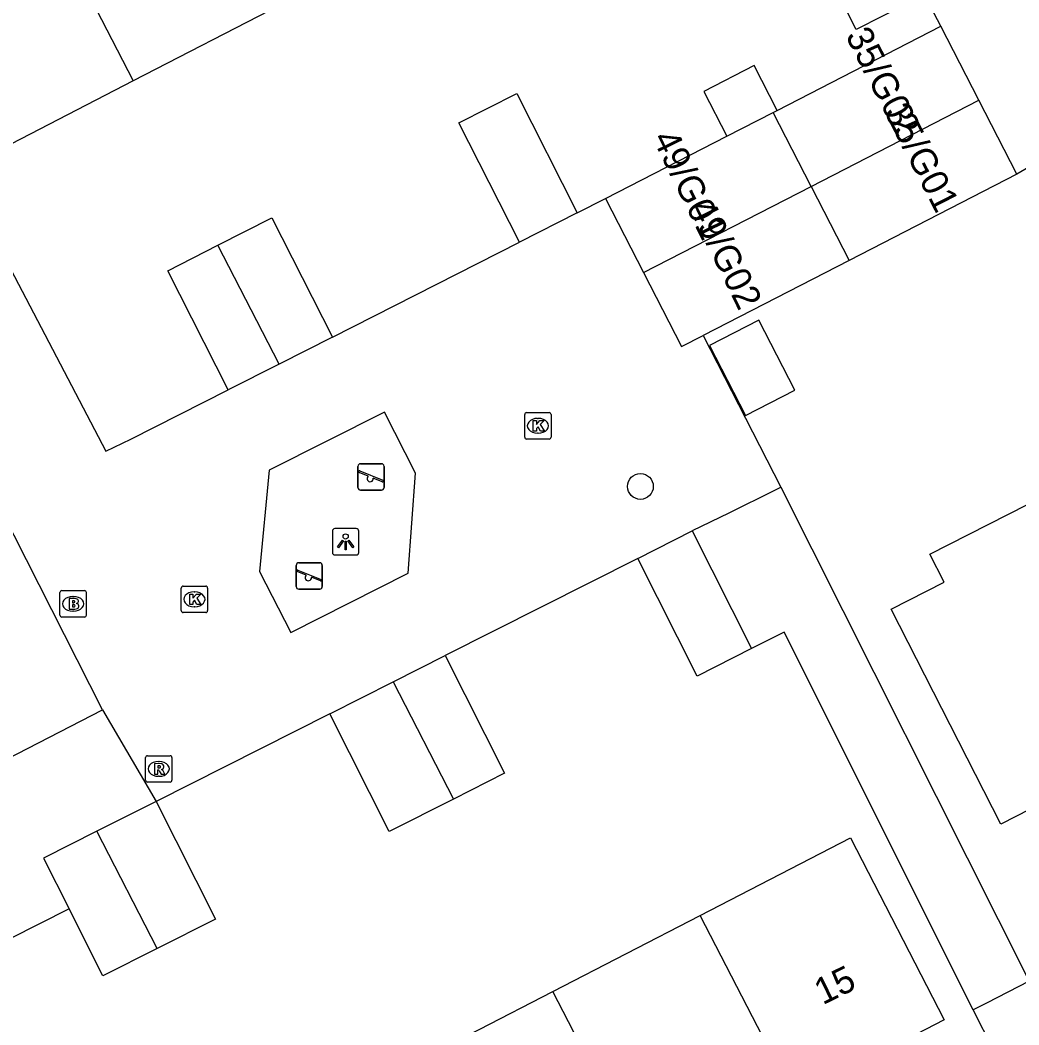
# Model space of a CAD drawing. Extents: x 158461 to 159795, y 387220 to 388672.
# Drawn here: x 159193.22 to 159231.02, y 387806.3 to 387844.32 of the extents above; entities that cross this region are included whole.
import ezdxf

# ---------------------------------------------------------------- set-up
doc = ezdxf.new("R2010")
doc.units = 0
for name, color, linetype in [('IMGEO_Boom', 7, 'Continuous'), ('IMGEO_Brandkraan', 7, 'Continuous'), ('IMGEO_Kolk', 7, 'Continuous'), ('IMGEO_Lichtpunt', 7, 'Continuous'), ('IMGEO_Pand', 7, 'Continuous'), ('IMGEO_Pand_nummerreeks', 7, 'Continuous'), ('IMGEO_Rijbaan_lokaal_open', 7, 'Continuous'), ('IMGEO_Rioolput', 7, 'Continuous'), ('IMGEO_Speelvoorziening', 7, 'Continuous'), ('IMGEO_Voetpad_open', 7, 'Continuous')]:
    doc.layers.add(name, color=color, linetype=linetype)

msp = doc.modelspace()

# ---------------------------------------------------------------- linework, layer by layer
at = {"layer": 'IMGEO_Boom'}
msp.add_circle((159216.693, 387826.671), 0.489, dxfattribs=at)
at = {"layer": 'IMGEO_Brandkraan'}
for p, q in [((159194.797, 387822.728), (159195.649, 387822.728)), ((159194.722, 387821.802), (159194.722, 387822.654)), ((159195.21, 387822.508), (159195.235, 387822.508)), ((159195.723, 387822.654), (159195.723, 387821.802)), ((159195.649, 387821.728), (159194.797, 387821.728)), ((159195.233, 387821.948), (159195.208, 387821.948))]:
    msp.add_line(p, q, dxfattribs=at)
for points in [[(159194.797, 387822.728), (159195.649, 387822.728)], [(159194.722, 387821.802), (159194.722, 387822.654)], [(159195.07, 387822.428), (159195.07, 387822.028), (159195.283, 387822.028)], [(159195.301, 387822.428), (159195.07, 387822.428)], [(159195.249, 387822.347), (159195.195, 387822.347), (159195.195, 387822.271)], [(159195.723, 387822.654), (159195.723, 387821.802)], [(159195.195, 387822.271), (159195.248, 387822.271)], [(159195.257, 387822.195), (159195.195, 387822.195), (159195.195, 387822.114)], [(159195.195, 387822.114), (159195.257, 387822.114)], [(159195.649, 387821.728), (159194.797, 387821.728)]]:
    msp.add_lwpolyline(points, dxfattribs=at)
for centre, radius, start, end in [((159194.799, 387822.652), 0.0765, 91.552, 178.448), ((159194.799, 387822.652), 0.0765, 91.552, 178.448), ((159195.647, 387822.652), 0.0765, 1.552, 88.448), ((159195.647, 387822.652), 0.0765, 1.552, 88.448), ((159195.25, 387822.309), 0.0379, 267.8285, 90.9355), ((159195.305, 387822.283), 0.145, 59.4692, 91.5367), ((159195.33, 387822.33), 0.0922, 285.5137, 58.1501), ((159195.258, 387822.154), 0.0404, 269.8759, 90.5077), ((159195.289, 387822.279), 0.251, 268.6676, 293.5347), ((159195.335, 387822.138), 0.105, 301.3115, 78.989), ((159194.799, 387821.804), 0.0765, 181.552, 268.448), ((159194.799, 387821.804), 0.0765, 181.552, 268.448), ((159195.647, 387821.804), 0.0765, 271.552, 358.448), ((159195.647, 387821.804), 0.0765, 271.552, 358.448)]:
    msp.add_arc(centre, radius, start, end, dxfattribs=at)
for centre, major_axis, ratio, start_param, end_param in [((159195.209, 387822.228), (-0.387, 0.002), 0.722429, 4.712389, 7.853982), ((159195.234, 387822.228), (-0.39, 0.002), 0.717154, 1.570796, 4.712389)]:
    msp.add_ellipse(centre, major_axis=major_axis, ratio=ratio, start_param=start_param, end_param=end_param, dxfattribs=at)
at = {"layer": 'IMGEO_Kolk'}
for p, q in [((159212.313, 387828.539), (159212.313, 387829.391)), ((159212.388, 387829.465), (159213.24, 387829.465)), ((159212.801, 387829.245), (159212.826, 387829.245)), ((159213.314, 387829.391), (159213.314, 387828.539)), ((159213.24, 387828.465), (159212.388, 387828.465)), ((159212.824, 387828.685), (159212.799, 387828.685)), ((159199.313, 387821.972), (159199.313, 387822.824)), ((159199.388, 387822.898), (159200.24, 387822.898)), ((159200.314, 387822.824), (159200.314, 387821.972)), ((159199.801, 387822.678), (159199.826, 387822.678)), ((159199.824, 387822.118), (159199.799, 387822.118)), ((159200.24, 387821.898), (159199.388, 387821.898))]:
    msp.add_line(p, q, dxfattribs=at)
for points in [[(159212.313, 387828.539), (159212.313, 387829.391)], [(159212.388, 387829.465), (159213.24, 387829.465)], [(159213.314, 387829.391), (159213.314, 387828.539)], [(159212.634, 387829.165), (159212.757, 387829.165), (159212.757, 387829.014), (159212.887, 387829.165), (159213.051, 387829.165), (159212.905, 387829.014), (159213.058, 387828.765), (159212.906, 387828.765), (159212.821, 387828.929), (159212.757, 387828.862), (159212.757, 387828.765), (159212.634, 387828.765), (159212.634, 387829.165)], [(159213.24, 387828.465), (159212.388, 387828.465)], [(159199.313, 387821.972), (159199.313, 387822.824)], [(159199.388, 387822.898), (159200.24, 387822.898)], [(159200.314, 387822.824), (159200.314, 387821.972)], [(159199.634, 387822.598), (159199.757, 387822.598), (159199.757, 387822.447), (159199.887, 387822.598), (159200.051, 387822.598), (159199.905, 387822.447), (159200.058, 387822.198), (159199.906, 387822.198), (159199.821, 387822.362), (159199.757, 387822.295), (159199.757, 387822.198), (159199.634, 387822.198), (159199.634, 387822.598)], [(159200.24, 387821.898), (159199.388, 387821.898)]]:
    msp.add_lwpolyline(points, dxfattribs=at)
for centre, start, end in [((159212.39, 387829.389), 91.552, 178.448), ((159212.39, 387829.389), 91.552, 178.448), ((159213.238, 387829.389), 1.552, 88.448), ((159213.238, 387829.389), 1.552, 88.448), ((159212.39, 387828.541), 181.552, 268.448), ((159212.39, 387828.541), 181.552, 268.448), ((159213.238, 387828.541), 271.552, 358.448), ((159213.238, 387828.541), 271.552, 358.448), ((159199.39, 387822.822), 91.552, 178.448), ((159199.39, 387822.822), 91.552, 178.448), ((159200.238, 387822.822), 1.552, 88.448), ((159200.238, 387822.822), 1.552, 88.448), ((159199.39, 387821.974), 181.552, 268.448), ((159199.39, 387821.974), 181.552, 268.448), ((159200.238, 387821.974), 271.552, 358.448), ((159200.238, 387821.974), 271.552, 358.448)]:
    msp.add_arc(centre, 0.0765, start, end, dxfattribs=at)
for centre, major_axis, ratio, start_param, end_param in [((159212.8, 387828.965), (-0.387, 0.002), 0.722429, 4.712389, 7.853982), ((159212.825, 387828.965), (-0.39, 0.002), 0.717154, 1.570796, 4.712389), ((159199.8, 387822.398), (-0.387, 0.002), 0.722429, 4.712389, 7.853982), ((159199.825, 387822.398), (-0.39, 0.002), 0.717154, 1.570796, 4.712389)]:
    msp.add_ellipse(centre, major_axis=major_axis, ratio=ratio, start_param=start_param, end_param=end_param, dxfattribs=at)
at = {"layer": 'IMGEO_Lichtpunt'}
for p, q in [((159205.94, 387825.074), (159205.132, 387825.074)), ((159205.94, 387825.074), (159205.132, 387825.074)), ((159205.038, 387824.979), (159205.038, 387824.172)), ((159205.038, 387824.979), (159205.038, 387824.172)), ((159206.034, 387824.172), (159206.034, 387824.979)), ((159206.034, 387824.172), (159206.034, 387824.979)), ((159205.132, 387824.078), (159205.94, 387824.078)), ((159205.132, 387824.078), (159205.94, 387824.078))]:
    msp.add_line(p, q, dxfattribs=at)
for points in [[(159205.412, 387824.643), (159205.451, 387824.615), (159205.263, 387824.353), (159205.225, 387824.38), (159205.412, 387824.643)], [(159205.624, 387824.615), (159205.662, 387824.642), (159205.849, 387824.38), (159205.81, 387824.352), (159205.624, 387824.615)], [(159205.514, 387824.595), (159205.561, 387824.595), (159205.561, 387824.273), (159205.514, 387824.273), (159205.514, 387824.595)]]:
    msp.add_lwpolyline(points, dxfattribs=at)
msp.add_circle((159205.537, 387824.777), 0.0994, dxfattribs=at)
for centre, start, end in [((159205.132, 387824.979), 90, 180), ((159205.132, 387824.979), 90, 180), ((159205.94, 387824.979), 0, 90), ((159205.94, 387824.979), 0, 90), ((159205.132, 387824.172), 180, 270), ((159205.132, 387824.172), 180, 270), ((159205.94, 387824.172), 270, 0), ((159205.94, 387824.172), 270, 360)]:
    msp.add_arc(centre, 0.0946, start, end, dxfattribs=at)
at = {"layer": 'IMGEO_Pand'}
for points in [[(159222.602, 387848.427), (159224.592, 387849.435), (159226.855, 387844.969), (159224.864, 387843.961), (159222.602, 387848.427)], [(159197.498, 387842.013), (159191.802, 387839.076), (159188.192, 387846.076), (159193.887, 387849.013)], [(159193.887, 387849.013), (159197.498, 387842.013)], [(159203.09, 387844.897), (159197.498, 387842.013)], [(159221.867, 387840.896), (159228.068, 387844.083)], [(159229.506, 387841.284), (159228.068, 387844.083)], [(159221.867, 387840.896), (159220.992, 387842.598), (159219.088, 387841.62), (159219.963, 387839.918)], [(159212.112, 387835.917), (159209.822, 387840.427), (159212.013, 387841.54), (159214.303, 387837.029)], [(159223.16, 387838.024), (159229.506, 387841.284)], [(159230.944, 387838.485), (159229.506, 387841.284)], [(159219.963, 387839.918), (159221.722, 387840.822)], [(159221.722, 387840.822), (159221.867, 387840.896)], [(159223.16, 387838.024), (159221.722, 387840.822)], [(159215.376, 387837.561), (159219.963, 387839.918)], [(159230.944, 387838.485), (159224.598, 387835.224)], [(159216.813, 387834.763), (159223.16, 387838.024)], [(159223.16, 387838.024), (159224.598, 387835.224)], [(159215.376, 387837.561), (159216.813, 387834.763)], [(159200.704, 387835.798), (159202.744, 387836.834), (159205.035, 387832.323)], [(159214.303, 387837.029), (159212.112, 387835.917)], [(159201.093, 387830.322), (159198.802, 387834.833), (159200.704, 387835.798)], [(159203.023, 387831.302), (159200.704, 387835.798)], [(159224.598, 387835.224), (159219.069, 387832.383)], [(159216.813, 387834.763), (159218.252, 387831.963), (159219.069, 387832.383)], [(159219.306, 387832.001), (159220.666, 387829.354), (159222.534, 387830.314), (159221.174, 387832.961), (159219.306, 387832.001)], [(159205.035, 387832.323), (159203.023, 387831.302)], [(159203.023, 387831.302), (159201.093, 387830.322)], [(159235.429, 387817.984), (159233.557, 387817.028), (159234.16, 387815.846), (159230.337, 387813.894), (159226.184, 387822.028), (159228.188, 387823.051), (159227.65, 387824.104), (159231.342, 387825.989)], [(159216.594, 387823.947), (159218.653, 387824.986)], [(159218.653, 387824.986), (159220.899, 387820.532)], [(159220.899, 387820.532), (159218.84, 387819.493), (159216.594, 387823.947)], [(159207.333, 387819.277), (159209.304, 387820.271)], [(159209.304, 387820.271), (159211.551, 387815.817), (159209.62, 387814.843)], [(159204.939, 387818.069), (159207.333, 387819.277)], [(159207.333, 387819.277), (159209.62, 387814.843)], [(159209.62, 387814.843), (159207.186, 387813.615), (159204.939, 387818.069)], [(159198.361, 387814.751), (159196.119, 387813.62)], [(159198.361, 387814.751), (159200.607, 387810.298), (159198.407, 387809.188)], [(159196.119, 387813.62), (159194.107, 387812.605), (159195.076, 387810.684)], [(159198.407, 387809.188), (159196.119, 387813.62)], [(159218.957, 387810.435), (159224.641, 387813.368), (159228.194, 387806.484), (159222.51, 387803.551)], [(159198.407, 387809.188), (159196.353, 387808.152), (159195.076, 387810.684)], [(159213.379, 387807.557), (159218.957, 387810.435)], [(159222.51, 387803.551), (159218.957, 387810.435)], [(159207.8, 387804.678), (159213.379, 387807.557)], [(159216.931, 387800.672), (159213.379, 387807.557)]]:
    msp.add_lwpolyline(points, dxfattribs=at)
at = {"layer": 'IMGEO_Rijbaan_lokaal_open'}
for points in [[(159187.86, 387850.144), (159185.514, 387848.933), (159196.467, 387828.005), (159197.412, 387828.453), (159201.093, 387830.322)], [(159228.068, 387844.083), (159227.45, 387845.27), (159234.049, 387848.612)], [(159196.339, 387818.215), (159183.884, 387842.763)], [(159231.781, 387838.979), (159230.944, 387838.485)], [(159214.303, 387837.029), (159215.376, 387837.561)], [(159205.035, 387832.323), (159212.112, 387835.917)], [(159219.069, 387832.383), (159222.003, 387826.64)], [(159208.187, 387827.174), (159207.008, 387829.481), (159202.647, 387827.282), (159202.277, 387823.454), (159203.458, 387821.143), (159207.904, 387823.385), (159208.187, 387827.174)], [(159222.003, 387826.64), (159221.992, 387826.635), (159221.766, 387826.522), (159220.036, 387825.659), (159218.653, 387824.986)], [(159216.594, 387823.947), (159209.304, 387820.271)], [(159176.533, 387808.013), (159196.339, 387818.215)], [(159196.339, 387818.215), (159198.361, 387814.751)], [(159204.939, 387818.069), (159198.361, 387814.751)], [(159195.076, 387810.684), (159188.293, 387807.264)]]:
    msp.add_lwpolyline(points, dxfattribs=at)
at = {"layer": 'IMGEO_Rioolput'}
for p, q in [((159197.963, 387815.556), (159197.963, 387816.408)), ((159198.038, 387816.482), (159198.89, 387816.482)), ((159198.451, 387816.262), (159198.476, 387816.262)), ((159198.964, 387816.408), (159198.964, 387815.556)), ((159198.474, 387815.702), (159198.449, 387815.702)), ((159198.89, 387815.482), (159198.038, 387815.482))]:
    msp.add_line(p, q, dxfattribs=at)
for points in [[(159197.963, 387815.556), (159197.963, 387816.408)], [(159198.038, 387816.482), (159198.89, 387816.482)], [(159198.964, 387816.408), (159198.964, 387815.556)], [(159198.552, 387816.18), (159198.3, 387816.182), (159198.3, 387815.782)], [(159198.3, 387815.782), (159198.424, 387815.782), (159198.424, 387815.944), (159198.435, 387815.944)], [(159198.478, 387816.101), (159198.424, 387816.101), (159198.424, 387816.02)], [(159198.424, 387816.02), (159198.476, 387816.02)], [(159198.482, 387815.915), (159198.553, 387815.782), (159198.693, 387815.782), (159198.628, 387815.908)], [(159198.89, 387815.482), (159198.038, 387815.482)]]:
    msp.add_lwpolyline(points, dxfattribs=at)
for centre, radius, start, end in [((159198.04, 387816.406), 0.0765, 91.552, 178.448), ((159198.04, 387816.406), 0.0765, 91.552, 178.448), ((159198.888, 387816.406), 0.0765, 1.552, 88.448), ((159198.888, 387816.406), 0.0765, 1.552, 88.448), ((159198.434, 387815.891), 0.0533, 26.0293, 88.6989), ((159198.46, 387816.209), 0.19, 274.7715, 282.9687), ((159198.484, 387816.005), 0.0964, 77.0061, 93.1865), ((159198.498, 387816.062), 0.0378, 276.6634, 79.6772), ((159198.551, 387816.07), 0.109, 350.3612, 89.416), ((159198.549, 387816.07), 0.112, 277.5842, 350.9817), ((159198.533, 387815.855), 0.108, 29.5134, 73.7905), ((159198.04, 387815.558), 0.0765, 181.552, 268.448), ((159198.04, 387815.558), 0.0765, 181.552, 268.448), ((159198.888, 387815.558), 0.0765, 271.552, 358.448), ((159198.888, 387815.558), 0.0765, 271.552, 358.448)]:
    msp.add_arc(centre, radius, start, end, dxfattribs=at)
for centre, major_axis, ratio, start_param, end_param in [((159198.45, 387815.982), (-0.387, 0.002), 0.722429, 4.712389, 7.853982), ((159198.475, 387815.982), (-0.39, 0.002), 0.717154, 1.570796, 4.712389)]:
    msp.add_ellipse(centre, major_axis=major_axis, ratio=ratio, start_param=start_param, end_param=end_param, dxfattribs=at)
at = {"layer": 'IMGEO_Speelvoorziening'}
for p, q in [((159206.002, 387826.63), (159206.002, 387827.43)), ((159206.002, 387827.43), (159206.002, 387826.63)), ((159206.102, 387827.53), (159206.892, 387827.53)), ((159206.892, 387827.53), (159206.102, 387827.53)), ((159206.992, 387827.43), (159206.992, 387826.63)), ((159206.992, 387826.63), (159206.992, 387827.43)), ((159206.385, 387827.058), (159206.046, 387827.195)), ((159206.071, 387827.255), (159206.947, 387826.902)), ((159206.923, 387826.842), (159206.583, 387826.979)), ((159206.892, 387826.53), (159206.102, 387826.53)), ((159206.102, 387826.53), (159206.892, 387826.53)), ((159203.664, 387822.882), (159203.664, 387823.682)), ((159203.664, 387823.682), (159203.664, 387822.882)), ((159203.733, 387823.507), (159204.609, 387823.154)), ((159203.764, 387823.782), (159204.554, 387823.782)), ((159204.554, 387823.782), (159203.764, 387823.782)), ((159204.654, 387823.682), (159204.654, 387822.882)), ((159204.654, 387822.882), (159204.654, 387823.682)), ((159204.047, 387823.31), (159203.708, 387823.447)), ((159204.585, 387823.094), (159204.245, 387823.231)), ((159204.554, 387822.782), (159203.764, 387822.782)), ((159203.764, 387822.782), (159204.554, 387822.782))]:
    msp.add_line(p, q, dxfattribs=at)
for centre, radius, start, end in [((159206.102, 387827.43), 0.1, 90, 180), ((159206.102, 387827.43), 0.1, 90, 180), ((159206.892, 387827.43), 0.1, 0, 90), ((159206.892, 387827.43), 0.1, 360, 90), ((159206.059, 387827.225), 0.0327, 68.078, 248.078), ((159206.464, 387826.968), 0.12, 130.9928, 5.1632), ((159206.935, 387826.872), 0.0327, 248.078, 68.078), ((159206.102, 387826.63), 0.1, 180, 270), ((159206.102, 387826.63), 0.1, 180, 270), ((159206.892, 387826.63), 0.1, 270, 0), ((159206.892, 387826.63), 0.1, 270, 0), ((159203.764, 387823.682), 0.1, 90, 180), ((159203.764, 387823.682), 0.1, 90, 180), ((159203.721, 387823.477), 0.0327, 68.078, 248.078), ((159204.554, 387823.682), 0.1, 0, 90), ((159204.554, 387823.682), 0.1, 360, 90), ((159204.126, 387823.22), 0.12, 130.9928, 5.1632), ((159204.597, 387823.124), 0.0327, 248.078, 68.078), ((159203.764, 387822.882), 0.1, 180, 270), ((159203.764, 387822.882), 0.1, 180, 270), ((159204.554, 387822.882), 0.1, 270, 0), ((159204.554, 387822.882), 0.1, 270, 0)]:
    msp.add_arc(centre, radius, start, end, dxfattribs=at)
at = {"layer": 'IMGEO_Voetpad_open'}
for points in [[(159222.003, 387826.64), (159231.405, 387807.948)], [(159229.292, 387806.869), (159222.131, 387821.154), (159220.899, 387820.532)], [(159231.405, 387807.948), (159229.788, 387807.122), (159229.292, 387806.869)], [(159184.183, 387774.695), (159186.197, 387775.791), (159186.627, 387775.2), (159191.082, 387777.895), (159190.838, 387778.376), (159191.529, 387778.714), (159191.735, 387778.258), (159192.968, 387779.018), (159192.776, 387779.434), (159195.055, 387780.729), (159200.377, 387784.101), (159230.052, 387805.353), (159229.292, 387806.869)]]:
    msp.add_lwpolyline(points, dxfattribs=at)

# ---------------------------------------------------------------- texts
at = {"layer": 'IMGEO_Pand_nummerreeks'}
for s, rotation, p in [('35/G02', 297.1523, (159224.437, 387843.726)), ('35/G01', 297.1497, (159225.903, 387840.856)), ('49/G01', 296.0006, (159217.135, 387839.85)), ('49/G02', 296.0033, (159218.51, 387837.221)), ('15', 26.103, (159223.593, 387807.036))]:
    msp.add_text(s, height=1, rotation=rotation, dxfattribs=at).set_placement(p)

doc.saveas('drawing.dxf')
